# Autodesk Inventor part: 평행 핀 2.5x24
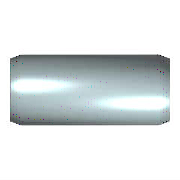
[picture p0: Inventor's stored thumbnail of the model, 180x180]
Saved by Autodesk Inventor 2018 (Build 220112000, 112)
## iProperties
IsCustomPart: 1
Created: 2012-02
Part Number: 평행 핀 2.5x24
Material: 강철, 연강
Description: 평행 핀
Document SubType Name: Modeling
Standard: KS B 1320
Designer: mduedu
Standards Organization: KS
Language: ko-KR
Size Designation: B 2.5 x  24
Categories: <MemberInstance><Categories><Category DisplayName="조임쇠" InternalName="e4da775c-781d-43d5-af7c-5136215cf5a6" Mnemonic="FSTN"><Category DisplayName="핀" InternalNa
Density: 1 g/cm^3
Appearance: Yellow
Author: mduedu
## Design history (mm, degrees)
sketch "스케치"
  geometry: C1 r 1.25 at (0, 0); 1 further point
  constraints: 1 centre point, 1 coincident
  dimensions: "d1" = 2.5 diameter of C1 (= NND)
extrude "본체" new body sketch "스케치" distance "d2" = 24 (= NLG); taper "d3" = 0 deg
chamfer "스케치2" distance "d8" = 0.4 (= PHH); stored, may be unused: angle "d9" = 15 deg (= FAWI), second distance "d12" = 0.4 (= PHH)
node "작업 평면1"
body "Solid1"
chamfer "모따기1" distance "d4" = 0.4 (= PHH); stored, may be unused: angle "d5" = 15 deg (= FAWI), second distance "d11" = 0.4 (= PHH)
other parameters: "NND" = 2.5 [user parameter; used in 1 equation term], "NLG" = 24 [user parameter; used in 1 equation term], "PHH" = 0.4 [user parameter; used in 4 equation terms], "FAWI" = 15 deg [user parameter; used in 2 equation terms], "d13" = 0, "d15" = 0, "d16" = 0, "KAH" = 0.3 [user parameter]
